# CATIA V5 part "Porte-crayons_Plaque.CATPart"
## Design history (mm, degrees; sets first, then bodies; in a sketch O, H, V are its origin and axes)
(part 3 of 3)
    line L1694 (40.3722, 77.9051) -> (40.2106, 77.9332)
    line L1695 (40.5369, 77.8832) -> (40.3722, 77.9051)
    line L1696 (40.7047, 77.8677) -> (40.5369, 77.8832)
    line L1697 (40.8755, 77.8583) -> (40.7047, 77.8677)
    line L1698 (41.0493, 77.8551) -> (40.8755, 77.8583)
    line L1699 (27.7898, 78.0146) -> (25.5976, 78.0146)
    line L1700 (25.8235, 81.4823) -> (27.7898, 78.0146)
    line L1701 (25.9615, 81.5465) -> (25.8235, 81.4823)
    line L1702 (26.0937, 81.617) -> (25.9615, 81.5465)
    line L1703 (26.2203, 81.6937) -> (26.0937, 81.617)
    line L1704 (26.3411, 81.7767) -> (26.2203, 81.6937)
    line L1705 (26.4562, 81.8659) -> (26.3411, 81.7767)
    line L1706 (26.5657, 81.9614) -> (26.4562, 81.8659)
    line L1707 (26.6694, 82.0631) -> (26.5657, 81.9614)
    line L1708 (26.7673, 82.171) -> (26.6694, 82.0631)
    line L1709 (26.8596, 82.2852) -> (26.7673, 82.171)
    line L1710 (26.9462, 82.4056) -> (26.8596, 82.2852)
    line L1711 (27.0257, 82.5326) -> (26.9462, 82.4056)
    line L1712 (27.0968, 82.6663) -> (27.0257, 82.5326)
    line L1713 (27.1596, 82.8068) -> (27.0968, 82.6663)
    line L1714 (27.214, 82.9541) -> (27.1596, 82.8068)
    line L1715 (27.2601, 83.1081) -> (27.214, 82.9541)
    line L1716 (27.2977, 83.2689) -> (27.2601, 83.1081)
    line L1717 (27.327, 83.4365) -> (27.2977, 83.2689)
    line L1718 (27.3479, 83.611) -> (27.327, 83.4365)
    line L1719 (27.3605, 83.7921) -> (27.3479, 83.611)
    line L1720 (27.3647, 83.98) -> (27.3605, 83.7921)
    line L1721 (27.362, 84.1316) -> (27.3647, 83.98)
    line L1722 (27.3541, 84.2782) -> (27.362, 84.1316)
    line L1723 (27.3408, 84.4197) -> (27.3541, 84.2782)
    line L1724 (27.3222, 84.5561) -> (27.3408, 84.4197)
    line L1725 (27.2983, 84.6875) -> (27.3222, 84.5561)
    line L1726 (27.269, 84.8139) -> (27.2983, 84.6875)
    line L1727 (27.2345, 84.9352) -> (27.269, 84.8139)
    line L1728 (27.1946, 85.0514) -> (27.2345, 84.9352)
    line L1729 (27.1494, 85.1626) -> (27.1946, 85.0514)
    line L1730 (27.0989, 85.2688) -> (27.1494, 85.1626)
    line L1731 (27.0439, 85.3703) -> (27.0989, 85.2688)
    line L1732 (26.9852, 85.4678) -> (27.0439, 85.3703)
    line L1733 (26.9228, 85.5611) -> (26.9852, 85.4678)
    line L1734 (26.8566, 85.6504) -> (26.9228, 85.5611)
    line L1735 (26.7868, 85.7354) -> (26.8566, 85.6504)
    line L1736 (26.7131, 85.8164) -> (26.7868, 85.7354)
    line L1737 (26.6358, 85.8933) -> (26.7131, 85.8164)
    line L1738 (26.5548, 85.966) -> (26.6358, 85.8933)
    line L1739 (26.47, 86.0347) -> (26.5548, 85.966)
    line L1740 (26.3815, 86.0992) -> (26.47, 86.0347)
    line L1741 (26.2896, 86.1598) -> (26.3815, 86.0992)
    line L1742 (26.1947, 86.2169) -> (26.2896, 86.1598)
    line L1743 (26.0967, 86.2704) -> (26.1947, 86.2169)
    line L1744 (25.9957, 86.3202) -> (26.0967, 86.2704)
    line L1745 (25.8916, 86.3666) -> (25.9957, 86.3202)
    line L1746 (25.7844, 86.4093) -> (25.8916, 86.3666)
    line L1747 (25.6742, 86.4484) -> (25.7844, 86.4093)
    line L1748 (25.561, 86.4839) -> (25.6742, 86.4484)
    line L1749 (25.4447, 86.5159) -> (25.561, 86.4839)
    line L1750 (25.3253, 86.5442) -> (25.4447, 86.5159)
    line L1751 (25.2035, 86.5695) -> (25.3253, 86.5442)
    line L1752 (25.08, 86.592) -> (25.2035, 86.5695)
    line L1753 (24.9548, 86.612) -> (25.08, 86.592)
    line L1754 (24.8278, 86.6293) -> (24.9548, 86.612)
    line L1755 (24.6992, 86.6439) -> (24.8278, 86.6293)
    line L1756 (24.5688, 86.6558) -> (24.6992, 86.6439)
    line L1757 (24.4366, 86.6651) -> (24.5688, 86.6558)
    line L1758 (24.3028, 86.6718) -> (24.4366, 86.6651)
    line L1759 (24.1672, 86.6758) -> (24.3028, 86.6718)
    line L1760 (24.0299, 86.6771) -> (24.1672, 86.6758)
    line L1761 (20.9076, 86.6771) -> (24.0299, 86.6771)
    line L1762 (20.9076, 78.0146) -> (20.9076, 86.6771)
    line L1763 (22.8607, 78.0146) -> (20.9076, 78.0146)
    line L1764 (22.8607, 81.1368) -> (22.8607, 78.0146)
    line L1765 (23.9369, 81.1368) -> (22.8607, 81.1368)
    line L1766 (25.5976, 78.0146) -> (23.9369, 81.1368)
    line L1767 (15.8137, 77.8651) -> (15.487, 77.8551)
    line L1768 (16.1244, 77.895) -> (15.8137, 77.8651)
    line L1769 (16.419, 77.9448) -> (16.1244, 77.895)
    line L1770 (16.6976, 78.0146) -> (16.419, 77.9448)
    line L1771 (16.9601, 78.1043) -> (16.6976, 78.0146)
    line L1772 (17.2064, 78.2139) -> (16.9601, 78.1043)
    line L1773 (17.4367, 78.3434) -> (17.2064, 78.2139)
    line L1774 (17.651, 78.4929) -> (17.4367, 78.3434)
    line L1775 (17.8491, 78.6623) -> (17.651, 78.4929)
    line L1776 (18.0312, 78.8516) -> (17.8491, 78.6623)
    line L1777 (18.1966, 79.0627) -> (18.0312, 78.8516)
    line L1778 (18.3445, 79.2975) -> (18.1966, 79.0627)
    line L1779 (18.475, 79.5559) -> (18.3445, 79.2975)
    line L1780 (18.5882, 79.838) -> (18.475, 79.5559)
    line L1781 (18.6839, 80.1437) -> (18.5882, 79.838)
    line L1782 (18.7622, 80.473) -> (18.6839, 80.1437)
    line L1783 (18.8232, 80.826) -> (18.7622, 80.473)
    line L1784 (18.8667, 81.2027) -> (18.8232, 80.826)
    line L1785 (18.8928, 81.603) -> (18.8667, 81.2027)
    line L1786 (18.9015, 82.027) -> (18.8928, 81.603)
    line L1787 (18.9015, 86.6771) -> (18.9015, 82.027)
    line L1788 (17.0148, 86.6771) -> (18.9015, 86.6771)
    line L1789 (17.0148, 81.8277) -> (17.0148, 86.6771)
    line L1790 (17.0109, 81.5803) -> (17.0148, 81.8277)
    line L1791 (16.9989, 81.3483) -> (17.0109, 81.5803)
    line L1792 (16.979, 81.1318) -> (16.9989, 81.3483)
    line L1793 (16.9511, 80.9306) -> (16.979, 81.1318)
    line L1794 (16.9152, 80.7449) -> (16.9511, 80.9306)
    line L1795 (16.8714, 80.5746) -> (16.9152, 80.7449)
    line L1796 (16.8195, 80.4196) -> (16.8714, 80.5746)
    line L1797 (16.7598, 80.2801) -> (16.8195, 80.4196)
    line L1798 (16.692, 80.156) -> (16.7598, 80.2801)
    line L1799 (16.6163, 80.0474) -> (16.692, 80.156)
    line L1800 (16.5332, 79.9514) -> (16.6163, 80.0474)
    line L1801 (16.4436, 79.8656) -> (16.5332, 79.9514)
    line L1802 (16.3472, 79.7899) -> (16.4436, 79.8656)
    line L1803 (16.2443, 79.7242) -> (16.3472, 79.7899)
    line L1804 (16.1346, 79.6687) -> (16.2443, 79.7242)
    line L1805 (16.0184, 79.6232) -> (16.1346, 79.6687)
    line L1806 (15.8955, 79.5879) -> (16.0184, 79.6232)
    line L1807 (15.766, 79.5627) -> (15.8955, 79.5879)
    line L1808 (15.6298, 79.5475) -> (15.766, 79.5627)
    line L1809 (15.487, 79.5425) -> (15.6298, 79.5475)
    line L1810 (15.3443, 79.5475) -> (15.487, 79.5425)
    line L1811 (15.2085, 79.5627) -> (15.3443, 79.5475)
    line L1812 (15.0796, 79.5879) -> (15.2085, 79.5627)
    line L1813 (14.9577, 79.6232) -> (15.0796, 79.5879)
    line L1814 (14.8426, 79.6687) -> (14.9577, 79.6232)
    line L1815 (14.7344, 79.7242) -> (14.8426, 79.6687)
    line L1816 (14.6332, 79.7899) -> (14.7344, 79.7242)
    line L1817 (14.5389, 79.8656) -> (14.6332, 79.7899)
    line L1818 (14.4514, 79.9514) -> (14.5389, 79.8656)
    line L1819 (14.3709, 80.0474) -> (14.4514, 79.9514)
    line L1820 (14.2977, 80.156) -> (14.3709, 80.0474)
    line L1821 (14.2322, 80.2801) -> (14.2977, 80.156)
    line L1822 (14.1744, 80.4197) -> (14.2322, 80.2801)
    line L1823 (14.1243, 80.5746) -> (14.1744, 80.4197)
    line L1824 (14.082, 80.7449) -> (14.1243, 80.5746)
    line L1825 (14.0473, 80.9306) -> (14.082, 80.7449)
    line L1826 (14.0203, 81.1318) -> (14.0473, 80.9306)
    line L1827 (14.001, 81.3483) -> (14.0203, 81.1318)
    line L1828 (13.9895, 81.5803) -> (14.001, 81.3483)
    line L1829 (13.9856, 81.8277) -> (13.9895, 81.5803)
    line L1830 (13.9856, 86.6771) -> (13.9856, 81.8277)
    line L1831 (12.0193, 86.6771) -> (13.9856, 86.6771)
    line L1832 (12.0193, 82.027) -> (12.0193, 86.6771)
    line L1833 (12.0282, 81.603) -> (12.0193, 82.027)
    line L1834 (12.0549, 81.2027) -> (12.0282, 81.603)
    line L1835 (12.0994, 80.826) -> (12.0549, 81.2027)
    line L1836 (12.1617, 80.473) -> (12.0994, 80.826)
    line L1837 (12.2418, 80.1437) -> (12.1617, 80.473)
    line L1838 (12.3398, 79.838) -> (12.2418, 80.1437)
    line L1839 (12.4555, 79.5559) -> (12.3398, 79.838)
    line L1840 (12.589, 79.2975) -> (12.4555, 79.5559)
    line L1841 (12.7403, 79.0627) -> (12.589, 79.2975)
    line L1842 (12.9095, 78.8516) -> (12.7403, 79.0627)
    line L1843 (13.0955, 78.6623) -> (12.9095, 78.8516)
    line L1844 (13.2974, 78.4929) -> (13.0955, 78.6623)
    line L1845 (13.5153, 78.3434) -> (13.2974, 78.4929)
    line L1846 (13.7492, 78.2139) -> (13.5153, 78.3434)
    line L1847 (13.9989, 78.1043) -> (13.7492, 78.2139)
    line L1848 (14.2647, 78.0146) -> (13.9989, 78.1043)
    line L1849 (14.5463, 77.9448) -> (14.2647, 78.0146)
    line L1850 (14.8439, 77.895) -> (14.5463, 77.9448)
    line L1851 (15.1575, 77.8651) -> (14.8439, 77.895)
    line L1852 (15.487, 77.8551) -> (15.1575, 77.8651)
    line L1853 (6.3727, 78.0146) -> (6.3727, 85.0296)
    line L1854 (8.3391, 78.0146) -> (6.3727, 78.0146)
    line L1855 (8.3391, 85.0296) -> (8.3391, 78.0146)
    line L1856 (10.7173, 85.0296) -> (8.3391, 85.0296)
    line L1857 (10.7173, 86.6771) -> (10.7173, 85.0296)
    line L1858 (3.9945, 86.6771) -> (10.7173, 86.6771)
    line L1859 (3.9945, 85.0296) -> (3.9945, 86.6771)
    line L1860 (6.3727, 85.0296) -> (3.9945, 85.0296)
    line L1861 (47.2889, 69.9399) -> (46.0161, 68.6671)
    line L1862 (46.4404, 70.7884) -> (45.1676, 69.5156)
    arc A10 centre (59.5926, 87.3347) radius 3.6 from (62.5268, 85.249) to (62.1382, 89.8803) ccw
    arc A11 centre (54.3953, 92.532) radius 3.6 from (56.9409, 95.0775) to (52.3096, 95.4662) ccw
    arc A12 centre (59.5926, 87.3347) radius 2.4 from (61.66, 86.1158) to (61.2896, 89.0318) ccw
    line L1863 (41.5489, 89.0193) -> (42.3974, 88.1708)
    line L1864 (42.3974, 88.1708) -> (48.0217, 93.7951)
    line L1865 (34.0077, 79.8082) -> (34.0077, 82.8906)
    line L1866 (33.9749, 79.7823) -> (34.0077, 79.8082)
    line L1867 (33.9402, 79.7577) -> (33.9749, 79.7823)
    line L1868 (33.9037, 79.7345) -> (33.9402, 79.7577)
    line L1869 (33.8653, 79.7126) -> (33.9037, 79.7345)
    line L1870 (33.825, 79.6919) -> (33.8653, 79.7126)
    line L1871 (33.7829, 79.6727) -> (33.825, 79.6919)
    line L1872 (33.7389, 79.6548) -> (33.7829, 79.6727)
    line L1873 (33.6931, 79.6381) -> (33.7389, 79.6548)
    line L1874 (33.6454, 79.6229) -> (33.6931, 79.6381)
    line L1875 (33.5958, 79.6089) -> (33.6454, 79.6229)
    line L1876 (33.5452, 79.5963) -> (33.5958, 79.6089)
    line L1877 (33.4943, 79.585) -> (33.5452, 79.5963)
    line L1878 (33.4432, 79.575) -> (33.4943, 79.585)
    line L1879 (33.3918, 79.5664) -> (33.4432, 79.575)
    line L1880 (33.3401, 79.5591) -> (33.3918, 79.5664)
    line L1881 (33.2881, 79.5531) -> (33.3401, 79.5591)
    line L1882 (33.2359, 79.5485) -> (33.2881, 79.5531)
    line L1883 (33.1834, 79.5452) -> (33.2359, 79.5485)
    line L1884 (33.1307, 79.5431) -> (33.1834, 79.5452)
    line L1885 (33.0777, 79.5425) -> (33.1307, 79.5431)
    line L1886 (32.8394, 79.5499) -> (33.0777, 79.5425)
    line L1887 (32.6135, 79.572) -> (32.8394, 79.5499)
    line L1888 (32.3999, 79.6089) -> (32.6135, 79.572)
    line L1889 (32.1987, 79.6605) -> (32.3999, 79.6089)
    line L1890 (32.0098, 79.7268) -> (32.1987, 79.6605)
    line L1891 (31.8333, 79.8079) -> (32.0098, 79.7268)
    line L1892 (31.6692, 79.9038) -> (31.8333, 79.8079)
    line L1893 (31.5174, 80.0144) -> (31.6692, 79.9038)
    line L1894 (31.3779, 80.1398) -> (31.5174, 80.0144)
    line L1895 (31.2509, 80.2799) -> (31.3779, 80.1398)
    line L1896 (31.136, 80.4334) -> (31.2509, 80.2799)
    line L1897 (31.0332, 80.599) -> (31.136, 80.4334)
    line L1898 (30.9425, 80.7767) -> (31.0332, 80.599)
    line L1899 (30.864, 80.9665) -> (30.9425, 80.7767)
    line L1900 (30.7975, 81.1683) -> (30.864, 80.9665)
    line L1901 (30.7431, 81.3823) -> (30.7975, 81.1683)
    line L1902 (30.7007, 81.6084) -> (30.7431, 81.3823)
    line L1903 (30.6705, 81.8465) -> (30.7007, 81.6084)
    line L1904 (30.6524, 82.0968) -> (30.6705, 81.8465)
    line L1905 (30.6463, 82.3591) -> (30.6524, 82.0968)
    line L1906 (30.648, 82.488) -> (30.6463, 82.3591)
    line L1907 (30.653, 82.6142) -> (30.648, 82.488)
    line L1908 (30.6613, 82.7378) -> (30.653, 82.6142)
    line L1909 (30.6729, 82.8587) -> (30.6613, 82.7378)
    line L1910 (30.6878, 82.9769) -> (30.6729, 82.8587)
    line L1911 (30.7061, 83.0925) -> (30.6878, 82.9769)
    line L1912 (30.7277, 83.2055) -> (30.7061, 83.0925)
    line L1913 (30.7526, 83.3157) -> (30.7277, 83.2055)
    line L1914 (30.7809, 83.4233) -> (30.7526, 83.3157)
    line L1915 (30.8124, 83.5283) -> (30.7809, 83.4233)
    line L1916 (30.847, 83.6303) -> (30.8124, 83.5283)
    line L1917 (30.8844, 83.7292) -> (30.847, 83.6303)
    line L1918 (30.9246, 83.8249) -> (30.8844, 83.7292)
    line L1919 (30.9676, 83.9173) -> (30.9246, 83.8249)
    line L1920 (31.0134, 84.0066) -> (30.9676, 83.9173)
    line L1921 (31.0619, 84.0927) -> (31.0134, 84.0066)
    line L1922 (31.1133, 84.1756) -> (31.0619, 84.0927)
    line L1923 (31.1674, 84.2553) -> (31.1133, 84.1756)
    line L1924 (31.2243, 84.3318) -> (31.1674, 84.2553)
    line L1925 (31.2841, 84.4052) -> (31.2243, 84.3318)
    line L1926 (31.3463, 84.4752) -> (31.2841, 84.4052)
    line L1927 (31.4108, 84.542) -> (31.3463, 84.4752)
    line L1928 (31.4776, 84.6055) -> (31.4108, 84.542)
    line L1929 (31.5466, 84.6656) -> (31.4776, 84.6055)
    line L1930 (31.6179, 84.7224) -> (31.5466, 84.6656)
    line L1931 (31.6914, 84.7759) -> (31.6179, 84.7224)
    line L1932 (31.7672, 84.826) -> (31.6914, 84.7759)
    line L1933 (31.8453, 84.8728) -> (31.7672, 84.826)
    line L1934 (31.9256, 84.9163) -> (31.8453, 84.8728)
    line L1935 (32.0081, 84.9565) -> (31.9256, 84.9163)
    line L1936 (32.0927, 84.9932) -> (32.0081, 84.9565)
    line L1937 (32.179, 85.0259) -> (32.0927, 84.9932)
    line L1938 (32.267, 85.0548) -> (32.179, 85.0259)
    line L1939 (32.3568, 85.0798) -> (32.267, 85.0548)
    line L1940 (32.4483, 85.101) -> (32.3568, 85.0798)
    line L1941 (32.5415, 85.1184) -> (32.4483, 85.101)
    line L1942 (32.6364, 85.1318) -> (32.5415, 85.1184)
    line L1943 (32.733, 85.1415) -> (32.6364, 85.1318)
    line L1944 (32.8314, 85.1473) -> (32.733, 85.1415)
    line L1945 (32.9315, 85.1492) -> (32.8314, 85.1473)
    line L1946 (33.0413, 85.1472) -> (32.9315, 85.1492)
    line L1947 (33.1473, 85.1412) -> (33.0413, 85.1472)
    line L1948 (33.2496, 85.1313) -> (33.1473, 85.1412)
    line L1949 (33.3482, 85.1173) -> (33.2496, 85.1313)
    line L1950 (33.443, 85.0994) -> (33.3482, 85.1173)
    line L1951 (33.5342, 85.0775) -> (33.443, 85.0994)
    line L1952 (33.6216, 85.0516) -> (33.5342, 85.0775)
    line L1953 (33.7053, 85.0216) -> (33.6216, 85.0516)
    line L1954 (33.7853, 84.9878) -> (33.7053, 85.0216)
    line L1955 (33.8616, 84.9499) -> (33.7853, 84.9878)
    line L1956 (33.9356, 84.9091) -> (33.8616, 84.9499)
    line L1957 (34.0088, 84.8665) -> (33.9356, 84.9091)
    line L1958 (34.0812, 84.822) -> (34.0088, 84.8665)
    line L1959 (34.1528, 84.7756) -> (34.0812, 84.822)
    line L1960 (34.2236, 84.7274) -> (34.1528, 84.7756)
    line L1961 (34.2936, 84.6773) -> (34.2236, 84.7274)
    line L1962 (34.3629, 84.6253) -> (34.2936, 84.6773)
    line L1963 (34.4312, 84.5715) -> (34.3629, 84.6253)
    line L1964 (34.4989, 84.5158) -> (34.4312, 84.5715)
    line L1965 (34.5657, 84.4583) -> (34.4989, 84.5158)
    line L1966 (35.5887, 85.7072) -> (34.5657, 84.4583)
    line L1967 (35.5012, 85.794) -> (35.5887, 85.7072)
    line L1968 (35.4086, 85.8789) -> (35.5012, 85.794)
    line L1969 (35.3109, 85.9619) -> (35.4086, 85.8789)
    line L1970 (35.2082, 86.0431) -> (35.3109, 85.9619)
    line L1971 (35.1005, 86.1224) -> (35.2082, 86.0431)
    line L1972 (34.9877, 86.1998) -> (35.1005, 86.1224)
    line L1973 (34.8698, 86.2755) -> (34.9877, 86.1998)
    line L1974 (34.7469, 86.3492) -> (34.8698, 86.2755)
    line L1975 (34.619, 86.4211) -> (34.7469, 86.3492)
    line L1976 (34.486, 86.4911) -> (34.619, 86.4211)
    line L1977 (34.3478, 86.5567) -> (34.486, 86.4911)
    line L1978 (34.2043, 86.6155) -> (34.3478, 86.5567)
    line L1979 (34.0555, 86.6673) -> (34.2043, 86.6155)
    line L1980 (33.9014, 86.7122) -> (34.0555, 86.6673)
    line L1981 (33.742, 86.7502) -> (33.9014, 86.7122)
    line L1982 (33.5772, 86.7813) -> (33.742, 86.7502)
    line L1983 (33.4072, 86.8054) -> (33.5772, 86.7813)
    line L1984 (33.2318, 86.8227) -> (33.4072, 86.8054)
    line L1985 (33.0511, 86.8331) -> (33.2318, 86.8227)
    line L1986 (32.8651, 86.8365) -> (33.0511, 86.8331)
    line L1987 (32.6933, 86.8335) -> (32.8651, 86.8365)
    line L1988 (32.5234, 86.8243) -> (32.6933, 86.8335)
    line L1989 (32.3553, 86.809) -> (32.5234, 86.8243)
    line L1990 (32.1891, 86.7876) -> (32.3553, 86.809)
    line L1991 (32.0248, 86.7601) -> (32.1891, 86.7876)
    line L1992 (31.8623, 86.7265) -> (32.0248, 86.7601)
    line L1993 (31.7016, 86.6868) -> (31.8623, 86.7265)
    line L1994 (31.5429, 86.6409) -> (31.7016, 86.6868)
    line L1995 (31.386, 86.589) -> (31.5429, 86.6409)
    line L1996 (31.2309, 86.5309) -> (31.386, 86.589)
    line L1997 (31.0787, 86.467) -> (31.2309, 86.5309)
    line L1998 (30.9304, 86.3976) -> (31.0787, 86.467)
    line L1999 (30.7859, 86.3225) -> (30.9304, 86.3976)
    line L2000 (30.6453, 86.2418) -> (30.7859, 86.3225)
    line L2001 (30.5085, 86.1556) -> (30.6453, 86.2418)
    line L2002 (30.3756, 86.0638) -> (30.5085, 86.1556)
    line L2003 (30.2465, 85.9664) -> (30.3756, 86.0638)
    line L2004 (30.1213, 85.8635) -> (30.2465, 85.9664)
    line L2005 (29.9999, 85.7549) -> (30.1213, 85.8635)
    line L2006 (29.8824, 85.6408) -> (29.9999, 85.7549)
    line L2007 (29.7693, 85.5213) -> (29.8824, 85.6408)
    line L2008 (29.661, 85.3966) -> (29.7693, 85.5213)
    line L2009 (29.5577, 85.2667) -> (29.661, 85.3966)
    line L2010 (29.4594, 85.1317) -> (29.5577, 85.2667)
    line L2011 (29.3659, 84.9914) -> (29.4594, 85.1317)
    line L2012 (29.2773, 84.846) -> (29.3659, 84.9914)
    line L2013 (29.1937, 84.6954) -> (29.2773, 84.846)
    line L2014 (29.115, 84.5396) -> (29.1937, 84.6954)
    line L2015 (29.0412, 84.3787) -> (29.115, 84.5396)
    line L2016 (28.9723, 84.2125) -> (29.0412, 84.3787)
    line L2017 (28.9092, 84.0415) -> (28.9723, 84.2125)
    line L2018 (28.8527, 83.8658) -> (28.9092, 84.0415)
    line L2019 (28.8029, 83.6854) -> (28.8527, 83.8658)
    line L2020 (28.7597, 83.5004) -> (28.8029, 83.6854)
    line L2021 (28.7232, 83.3107) -> (28.7597, 83.5004)
    line L2022 (28.6933, 83.1164) -> (28.7232, 83.3107)
    line L2023 (28.67, 82.9175) -> (28.6933, 83.1164)
    line L2024 (28.6534, 82.7139) -> (28.67, 82.9175)
    line L2025 (28.6435, 82.5056) -> (28.6534, 82.7139)
    line L2026 (28.6401, 82.2927) -> (28.6435, 82.5056)
    line L2027 (28.6434, 82.0774) -> (28.6401, 82.2927)
    line L2028 (28.6531, 81.8673) -> (28.6434, 82.0774)
    line L2029 (28.6694, 81.6623) -> (28.6531, 81.8673)
    line L2030 (28.6922, 81.4626) -> (28.6694, 81.6623)
    line L2031 (28.7215, 81.268) -> (28.6922, 81.4626)
    line L2032 (28.7573, 81.0786) -> (28.7215, 81.268)
    line L2033 (28.7997, 80.8944) -> (28.7573, 81.0786)
    line L2034 (28.8485, 80.7154) -> (28.7997, 80.8944)
    line L2035 (28.9038, 80.5415) -> (28.8485, 80.7154)
    line L2036 (28.9656, 80.3729) -> (28.9038, 80.5415)
    line L2037 (29.0332, 80.2095) -> (28.9656, 80.3729)
    line L2038 (29.1057, 80.0516) -> (29.0332, 80.2095)
    line L2039 (29.1831, 79.8992) -> (29.1057, 80.0516)
    line L2040 (29.2654, 79.7521) -> (29.1831, 79.8992)
    line L2041 (29.3526, 79.6106) -> (29.2654, 79.7521)
    line L2042 (29.4447, 79.4744) -> (29.3526, 79.6106)
    line L2043 (29.5418, 79.3438) -> (29.4447, 79.4744)
    line L2044 (29.6438, 79.2186) -> (29.5418, 79.3438)
    line L2045 (29.7507, 79.0988) -> (29.6438, 79.2186)
    line L2046 (29.8625, 78.9845) -> (29.7507, 79.0988)
    line L2047 (29.9788, 78.8756) -> (29.8625, 78.9845)
    line L2048 (30.0992, 78.7722) -> (29.9788, 78.8756)
    line L2049 (30.2238, 78.6742) -> (30.0992, 78.7722)
    line L2050 (30.3525, 78.5816) -> (30.2238, 78.6742)
    line L2051 (30.4852, 78.4946) -> (30.3525, 78.5816)
    line L2052 (30.6222, 78.4129) -> (30.4852, 78.4946)
    line L2053 (30.7632, 78.3367) -> (30.6222, 78.4129)
    line L2054 (30.9083, 78.266) -> (30.7632, 78.3367)
    line L2055 (31.0576, 78.2007) -> (30.9083, 78.266)
    line L2056 (31.211, 78.1408) -> (31.0576, 78.2007)
    line L2057 (31.3676, 78.0865) -> (31.211, 78.1408)
    line L2058 (31.5264, 78.038) -> (31.3676, 78.0865)
    line L2059 (31.6875, 77.9951) -> (31.5264, 78.038)
    line L2060 (31.8509, 77.958) -> (31.6875, 77.9951)
    line L2061 (32.0165, 77.9266) -> (31.8509, 77.958)
    line L2062 (32.1843, 77.9009) -> (32.0165, 77.9266)
    line L2063 (32.3545, 77.8809) -> (32.1843, 77.9009)
    line L2064 (32.5268, 77.8666) -> (32.3545, 77.8809)
    line L2065 (32.7015, 77.858) -> (32.5268, 77.8666)
    line L2066 (32.8784, 77.8551) -> (32.7015, 77.858)
    line L2067 (33.06, 77.8582) -> (32.8784, 77.8551)
    line L2068 (33.2382, 77.8674) -> (33.06, 77.8582)
    line L2069 (33.4129, 77.8827) -> (33.2382, 77.8674)
    line L2070 (33.5841, 77.904) -> (33.4129, 77.8827)
    line L2071 (33.7519, 77.9315) -> (33.5841, 77.904)
    line L2072 (33.9163, 77.9652) -> (33.7519, 77.9315)
    line L2073 (34.0772, 78.0049) -> (33.9163, 77.9652)
    line L2074 (34.2346, 78.0507) -> (34.0772, 78.0049)
    line L2075 (34.3886, 78.1027) -> (34.2346, 78.0507)
    line L2076 (34.5391, 78.1607) -> (34.3886, 78.1027)
    line L2077 (34.685, 78.2232) -> (34.5391, 78.1607)
    line L2078 (34.8251, 78.2883) -> (34.685, 78.2232)
    line L2079 (34.9593, 78.356) -> (34.8251, 78.2883)
    line L2080 (35.0876, 78.4265) -> (34.9593, 78.356)
    line L2081 (35.2101, 78.4995) -> (35.0876, 78.4265)
    line L2082 (35.3267, 78.5753) -> (35.2101, 78.4995)
    line L2083 (35.4375, 78.6537) -> (35.3267, 78.5753)
    line L2084 (35.5425, 78.7347) -> (35.4375, 78.6537)
    line L2085 (35.6416, 78.8184) -> (35.5425, 78.7347)
    line L2086 (35.7349, 78.9048) -> (35.6416, 78.8184)
    line L2087 (35.7349, 82.8906) -> (35.7349, 78.9048)
    line L2088 (34.0077, 82.8906) -> (35.7349, 82.8906)
    point P4200 (48.0217, 93.7951)
    arc A13 centre (45.9101, 91.2592) radius 3.3 from (46.9279, 94.3983) to (43.5766, 93.5926) ccw
    point P4201 (46.9279, 94.3983)
    point P4203 (48.8729, 94.6462)
    arc A14 centre (45.9101, 91.2592) radius 4.5 from (47.8494, 95.3198) to (42.7281, 94.4412) ccw
    point P4204 (47.8494, 95.3198)
    point P4206 (50.1527, 93.3805)
    line L2089 (51.0012, 92.532) -> (59.5926, 83.9406)
    point P4207 (51.0012, 92.532)
    line L2090 (50.1527, 91.6834) -> (58.7441, 83.0921)
    point P4208 (50.1527, 91.6834)
    point P4209 (51.4255, 94.6533)
    line L2091 (52.274, 93.8048) -> (60.8654, 85.2134)
    point P4210 (52.274, 93.8048)
    point P4211 (60.8654, 85.2134)
    line L2092 (61.7139, 84.3649) -> (62.9867, 83.0921)
    point P4212 (61.7139, 84.3649)
    point P4213 (61.66, 86.1158)
    line L2093 (62.5268, 85.249) -> (64.6838, 83.0921)
    point P4214 (62.5268, 85.249)
    point P4215 (59.5926, 83.9406)
    line L2094 (60.4411, 83.0921) -> (61.5018, 82.0314)
    point P4216 (60.4411, 83.0921)
    point P4217 (58.7441, 83.0921)
    line L2095 (59.5926, 82.2436) -> (60.6533, 81.1829)
    point P4218 (61.4589, 79.8673)
    arc A15 centre (58.3198, 78.8495) radius 3.3 from (60.8557, 80.9611) to (60.6533, 81.1829) ccw
    point P4219 (60.8557, 80.9611)
    point P4221 (62.3805, 80.7888)
    arc A16 centre (58.3198, 78.8495) radius 4.5 from (61.7068, 81.8122) to (61.5018, 82.0314) ccw
    point P4222 (61.7068, 81.8122)
    point P4224 (49.4199, 69.5253)
    arc A17 centre (51.5316, 72.0612) radius 3.3 from (50.5138, 68.9221) to (53.865, 69.7278) ccw
    point P4225 (50.5138, 68.9221)
    point P4227 (48.5688, 68.6742)
    arc A18 centre (51.5316, 72.0612) radius 4.5 from (49.5922, 68.0006) to (54.7136, 68.8792) ccw
    point P4228 (49.5922, 68.0006)
    point P4230 (47.2889, 69.9399)
    line L2096 (46.4404, 70.7884) -> (42.1595, 75.0693)
    point P4231 (46.4404, 70.7884)
    point P4232 (48.1375, 70.7884)
    line L2097 (47.2889, 71.637) -> (43.0081, 75.9178)
    point P4233 (46.0161, 68.6671)
    line L2098 (45.1676, 69.5156) -> (38.7654, 75.9178)
    point P4234 (45.1676, 69.5156)
    point P4235 (45.132, 67.8542)
    line L2099 (44.2652, 68.721) -> (37.9169, 75.0693)
    point P4236 (44.2652, 68.721)
    point P4237 (52.3096, 95.4662)
    line L2100 (53.1765, 94.5994) -> (61.66, 86.1158)
    point P4238 (53.1765, 94.5994)
    coincidence: L1864 P4200, L1 P4201, A1 A13, L20 P4203, L3 P4204, A5 A14, L33 P4206, L34 P4207, L13 L2089, L29 P4208, L16 L2090, L33 P4209, L34 P4210, L21 L2091, L31 P4211, L32 P4212, L2091 L2092, A12 P4213, A10 P4214, L4 L2093, L31 P4215, L32 P4216, L2089 L2094, L38 P4217, L2090 L2095, L35 P4218, L36 P4219, A6 A15, L6 P4221, L22 P4222, A4 A16, L36 P4224, L35 P4225, A7 A17, L23 P4227, L8 P4228, A3 A18, L1861 P4230, L1862 P4231, L11 L2096, L37 P4232, L18 L2097, L1861 P4233, L1862 P4234, L24 L2098, A9 P4235, A2 P4236, L9 L2099, A11 P4237, A8 P4238, L4 L2100
  CutOut3 "Logo": Direction Sketch4, EndLimit length 0.2, Orientation true, Profile Sketch4, StartLimit length 0
Body2 "Plaque"
  Solid1 "Solide.2 ( Vue à plat )": linked copy from another document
